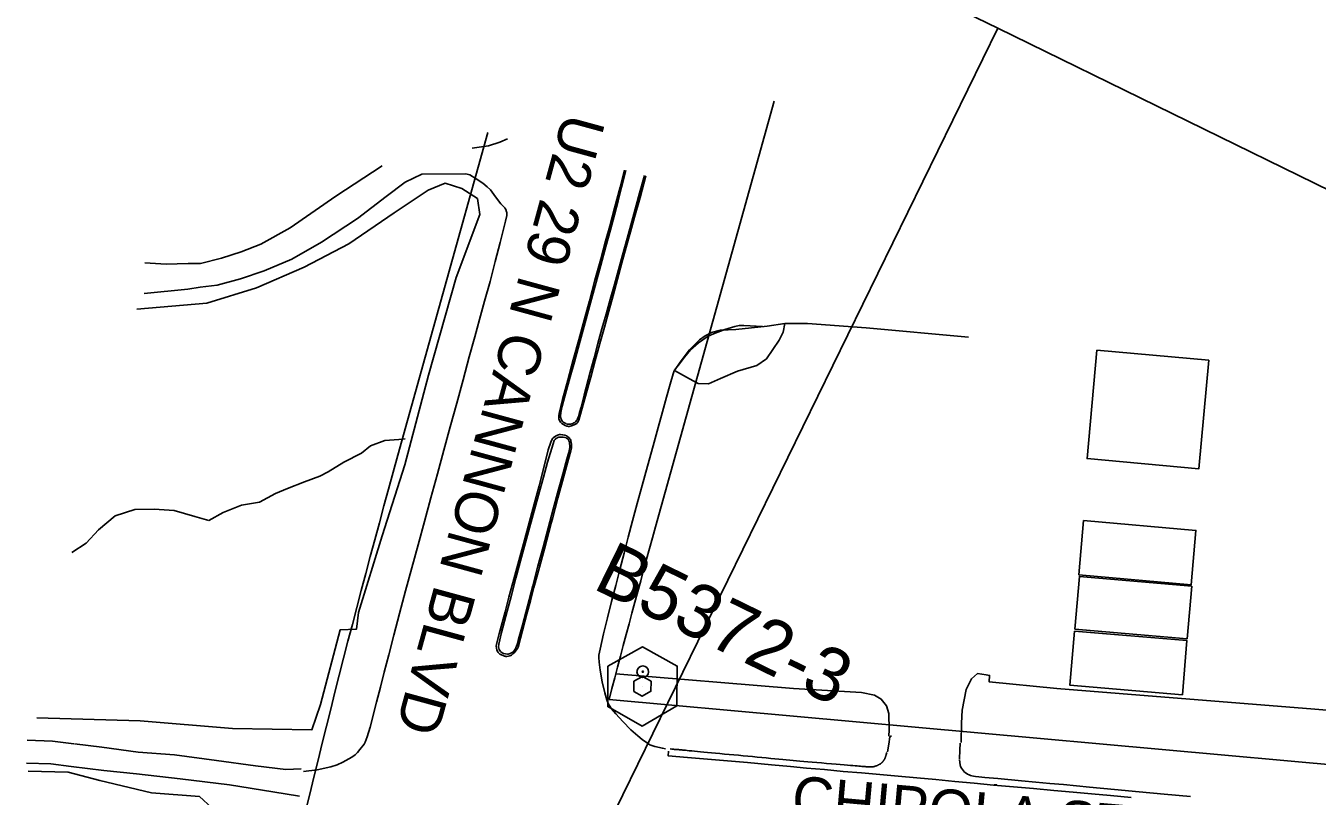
# Model space of a CAD drawing. Extents: x 1517485 to 1521905, y 636528 to 640355.
# Drawn here: x 1520407.4 to 1520890.3, y 638790.2 to 639078.4 of the extents above; entities that cross this region are included whole.
import ezdxf

# ---------------------------------------------------------------- set-up
doc = ezdxf.new("R2010")
doc.units = 0
for name, color, linetype in [('CTL Primary Horizontal and Vertical CELL', 7, 'Continuous'), ('CTL Primary Horizontal and Vertical Text', 7, 'Continuous'), ('Default', 7, 'Continuous'), ('Exist Building Metal Canopy', 7, 'Continuous'), ('Exist Hydro Stream or Body of Water', 7, 'Continuous'), ('Exist Right of Way Line', 7, 'Continuous'), ('Exist Roads Curbs', 7, 'Continuous'), ('Exist Roads EOP', 7, 'Continuous'), ('Exist Roads EOP Other', 7, 'Continuous'), ('Exist Roads EOP Text', 7, 'Continuous'), ('Exist Roads Soil', 7, 'Continuous'), ('Exist Vegetation Woods Line', 7, 'Continuous'), ('Scratch_Level_3', 7, 'Continuous')]:
    doc.layers.add(name, color=color, linetype=linetype)

msp = doc.modelspace()

# ---------------------------------------------------------------- linework, layer by layer
at = {"layer": 'CTL Primary Horizontal and Vertical CELL'}
msp.add_line((1520637.94, 638831.29), (1520637.94, 638831.29), dxfattribs=at)
msp.add_lwpolyline([(1520625.02, 638838.78), (1520638.02, 638846.03), (1520651.02, 638838.88), (1520650.82, 638823.98), (1520637.82, 638816.43), (1520625.02, 638823.68)], close=True, dxfattribs=at)
at = {"layer": 'Default'}
msp.add_line((1520637.94, 638831.29), (1520637.94, 638831.29), dxfattribs=at)
msp.add_lwpolyline([(1520634.71, 638833.16), (1520637.96, 638834.98), (1520641.21, 638833.19), (1520641.16, 638829.46), (1520637.91, 638827.58), (1520634.71, 638829.39)], close=True, dxfattribs=at)
for radius in [2.18, 0.24]:
    msp.add_circle((1520638.12, 638836.73), radius, dxfattribs=at)
at = {"layer": 'Exist Building Metal Canopy'}
for points in [[(1520807.97, 638957.02), (1520849.77, 638953.23), (1520846.08, 638912.69), (1520804.27, 638916.48)], [(1520802.95, 638893.33), (1520844.95, 638889.59), (1520843.14, 638869.31), (1520801.14, 638873.05)], [(1520841.7, 638849), (1520799.69, 638852.67), (1520801.41, 638872.41), (1520843.42, 638868.74)], [(1520799.56, 638851.92), (1520841.61, 638848.38), (1520839.9, 638828.12), (1520797.85, 638831.66)]]:
    msp.add_lwpolyline(points, close=True, dxfattribs=at)
at = {"layer": 'Exist Hydro Stream or Body of Water'}
for points in [[(1520475.78, 638893.36), (1520481.2, 638896.26), (1520488, 638899.1), (1520494.8, 638900.19), (1520500.81, 638903.46), (1520505.27, 638905.3), (1520511.57, 638907.78), (1520517.29, 638909.85), (1520520.5, 638911.55), (1520526.36, 638915.15), (1520532.89, 638918.5), (1520536.28, 638921.26), (1520541.69, 638923.18), (1520546.85, 638923.62), (1520549.25, 638923.85)], [(1520475.78, 638893.36), (1520470.63, 638894.79), (1520462.91, 638897.11), (1520455.32, 638897.57), (1520448.13, 638897.4), (1520440.85, 638895.01), (1520434.56, 638889.88), (1520429.96, 638884.82), (1520424.55, 638881.35)]]:
    msp.add_lwpolyline(points, dxfattribs=at)
at = {"layer": 'Exist Right of Way Line'}
for p, q in [((1520687.22, 639050.19), (1520642.88, 638890.91)), ((1520580.17, 639038.51), (1520546.55, 638917.73)), ((1520625.53, 638826.37), (1520958.51, 638796.3))]:
    msp.add_line(p, q, dxfattribs=at)
for radius, end in [(3851.74, 170.68088), (3751.74, 165.46414)]:
    msp.add_arc((1524257.18, 637884.74), radius, 164.44356, end, dxfattribs=at)
at = {"layer": 'Exist Roads Curbs'}
for points in [[(1520638.7, 639022.42), (1520636.89, 639015.82), (1520634.37, 639006.59), (1520632.25, 638998.85), (1520630.54, 638992.59), (1520629.03, 638987.06), (1520627.5, 638981.54), (1520625.95, 638976.01), (1520624.39, 638970.48), (1520622.85, 638964.97), (1520621.35, 638959.51), (1520619.89, 638954.11), (1520618.47, 638948.76), (1520616.22, 638940.17), (1520615.03, 638935.72), (1520614.46, 638933.66), (1520614.06, 638932.25), (1520613.73, 638931.31), (1520613.56, 638930.96), (1520613.38, 638930.69), (1520613.04, 638930.31), (1520612.9, 638930.17), (1520612.64, 638930.01), (1520612.33, 638929.83), (1520611.97, 638929.63), (1520611.58, 638929.46), (1520611.16, 638929.33), (1520610.93, 638929.3), (1520610.43, 638929.29), (1520609.94, 638929.35), (1520609.49, 638929.45), (1520609.27, 638929.54), (1520608.79, 638929.79), (1520608.53, 638929.96), (1520608.27, 638930.17), (1520608.05, 638930.41), (1520607.85, 638930.69), (1520607.68, 638930.99), (1520607.55, 638931.31), (1520607.45, 638931.62), (1520607.39, 638931.92), (1520607.37, 638932.48), (1520607.39, 638932.91), (1520607.43, 638933.25), (1520607.5, 638933.66), (1520607.61, 638934.33), (1520608.02, 638936.03), (1520608.87, 638939.35), (1520610.96, 638947.02), (1520612.53, 638952.65), (1520614.31, 638959.11), (1520616.21, 638966.01), (1520618.21, 638973.36), (1520620.33, 638981.15), (1520622.4, 638988.82), (1520624.29, 638995.8), (1520625.99, 639002.09), (1520627.5, 639007.7), (1520628.88, 639012.89), (1520630.18, 639017.93), (1520631.71, 639024.21)], [(1520729.39, 638806.53), (1520729.15, 638805.75), (1520729.09, 638805.56), (1520729.05, 638805.43), (1520729, 638805.3), (1520728.96, 638805.18), (1520728.93, 638805.07), (1520728.89, 638804.97), (1520728.85, 638804.87), (1520728.82, 638804.77), (1520728.78, 638804.67), (1520728.74, 638804.57), (1520728.7, 638804.47), (1520728.66, 638804.37), (1520728.61, 638804.27), (1520728.57, 638804.17), (1520728.52, 638804.06), (1520728.47, 638803.96), (1520728.42, 638803.86), (1520728.37, 638803.77), (1520728.31, 638803.67), (1520728.25, 638803.58), (1520728.19, 638803.49), (1520728.13, 638803.4), (1520728.06, 638803.31), (1520727.99, 638803.22), (1520727.9, 638803.12), (1520727.81, 638803.02), (1520727.71, 638802.92), (1520727.6, 638802.82), (1520727.49, 638802.71), (1520727.36, 638802.61), (1520727.23, 638802.5), (1520727.1, 638802.39), (1520726.96, 638802.29), (1520726.81, 638802.2), (1520726.66, 638802.11), (1520726.51, 638802.02), (1520726.35, 638801.94), (1520726.19, 638801.86), (1520726.03, 638801.79), (1520725.88, 638801.72), (1520725.73, 638801.65), (1520725.58, 638801.59), (1520725.45, 638801.54), (1520725.31, 638801.49), (1520725.18, 638801.44), (1520725.06, 638801.4), (1520724.94, 638801.37), (1520724.83, 638801.33), (1520724.72, 638801.3), (1520724.61, 638801.27), (1520724.5, 638801.25), (1520724.4, 638801.22), (1520724.3, 638801.2), (1520724.2, 638801.19), (1520724.1, 638801.17), (1520724, 638801.16), (1520723.9, 638801.15), (1520723.8, 638801.14), (1520723.7, 638801.13), (1520723.59, 638801.12), (1520723.48, 638801.12), (1520723.36, 638801.12), (1520723.23, 638801.12), (1520723.08, 638801.12), (1520722.91, 638801.13), (1520722.71, 638801.14), (1520722.49, 638801.15), (1520722.24, 638801.16), (1520721.97, 638801.18), (1520721.66, 638801.2), (1520721.32, 638801.23), (1520720.93, 638801.26), (1520720.5, 638801.29), (1520720.01, 638801.33), (1520719.47, 638801.38), (1520718.89, 638801.43), (1520718.25, 638801.48), (1520717.54, 638801.55), (1520716.72, 638801.62), (1520715.77, 638801.7), (1520714.67, 638801.8), (1520713.4, 638801.9), (1520711.98, 638802.02), (1520710.41, 638802.16), (1520708.67, 638802.31), (1520706.84, 638802.46), (1520704.99, 638802.62), (1520703.17, 638802.77), (1520701.45, 638802.92), (1520699.83, 638803.06), (1520698.31, 638803.19), (1520696.89, 638803.32), (1520695.57, 638803.43), (1520694.31, 638803.55), (1520693.06, 638803.66), (1520691.79, 638803.78), (1520690.43, 638803.9), (1520689.01, 638804.03), (1520687.51, 638804.18), (1520685.94, 638804.33), (1520684.3, 638804.48), (1520682.6, 638804.65), (1520680.86, 638804.81), (1520679.11, 638804.98), (1520677.36, 638805.15), (1520675.6, 638805.31), (1520673.85, 638805.48), (1520672.11, 638805.64), (1520670.36, 638805.8), (1520668.63, 638805.96), (1520666.95, 638806.12), (1520665.33, 638806.27), (1520663.8, 638806.41), (1520662.35, 638806.55), (1520660.99, 638806.68), (1520659.71, 638806.8), (1520658.51, 638806.92), (1520657.41, 638807.03), (1520656.41, 638807.12), (1520655.51, 638807.21), (1520654.72, 638807.29), (1520654.05, 638807.36), (1520653.49, 638807.42), (1520653.04, 638807.46), (1520652.7, 638807.49), (1520652.44, 638807.52), (1520652.25, 638807.54), (1520652.08, 638807.55), (1520651.92, 638807.57), (1520651.76, 638807.58), (1520651.6, 638807.6), (1520651.45, 638807.61), (1520651.29, 638807.62), (1520651.13, 638807.63), (1520650.93, 638807.64), (1520650.69, 638807.66), (1520650.38, 638807.68), (1520650.01, 638807.71), (1520649.58, 638807.75), (1520649.01, 638807.8), (1520648.31, 638807.86)], [(1520756.55, 638803.95), (1520756.63, 638802.78), (1520756.76, 638801.95), (1520756.98, 638801.29), (1520757.27, 638800.7), (1520757.62, 638800.15), (1520758.02, 638799.64), (1520758.47, 638799.18), (1520758.99, 638798.78), (1520759.54, 638798.44), (1520760.11, 638798.18), (1520760.67, 638797.97), (1520761.22, 638797.81), (1520761.82, 638797.68), (1520762.52, 638797.58), (1520763.79, 638797.45), (1520766.05, 638797.22), (1520770.86, 638796.76), (1520779.75, 638795.95), (1520785.15, 638795.46), (1520790.38, 638794.98), (1520795.46, 638794.5), (1520805.2, 638793.57), (1520814.57, 638792.69), (1520823.7, 638791.86), (1520833.15, 638791), (1520842.96, 638790.11)]]:
    msp.add_lwpolyline(points, dxfattribs=at)
msp.add_lwpolyline([(1520609.34, 638914.83), (1520608.2, 638910.7), (1520606.61, 638904.88), (1520604.64, 638897.61), (1520602.7, 638890.39), (1520600.83, 638883.4), (1520598.92, 638876.23), (1520596.96, 638868.83), (1520594.97, 638861.32), (1520593.07, 638854.15), (1520591.92, 638849.84), (1520591.52, 638848.38), (1520591.21, 638847.34), (1520590.9, 638846.35), (1520590.64, 638845.62), (1520590.42, 638845.15), (1520590.17, 638844.78), (1520589.89, 638844.47), (1520589.58, 638844.18), (1520589.25, 638843.91), (1520588.77, 638843.65), (1520588.47, 638843.51), (1520588.14, 638843.4), (1520587.81, 638843.33), (1520587.46, 638843.31), (1520586.77, 638843.38), (1520586.19, 638843.5), (1520585.95, 638843.58), (1520585.72, 638843.7), (1520585.47, 638843.87), (1520584.92, 638844.37), (1520584.65, 638844.71), (1520584.44, 638845.1), (1520584.29, 638845.55), (1520584.2, 638846.06), (1520584.27, 638847.01), (1520585.24, 638851.42), (1520587.33, 638859.34), (1520588.84, 638864.94), (1520590.67, 638871.71), (1520592.81, 638879.62), (1520595.04, 638887.86), (1520597.14, 638895.58), (1520599.1, 638902.79), (1520600.93, 638909.48), (1520602.51, 638915.16), (1520604.55, 638922.03), (1520605.01, 638923.22), (1520605.3, 638923.61), (1520605.63, 638923.93), (1520605.98, 638924.17), (1520606.36, 638924.34), (1520606.76, 638924.44), (1520607.16, 638924.5), (1520607.56, 638924.52), (1520608.35, 638924.44), (1520608.97, 638924.33), (1520609.42, 638924.19), (1520609.62, 638924.1), (1520609.81, 638923.98), (1520610, 638923.84), (1520610.17, 638923.68), (1520610.31, 638923.5), (1520610.42, 638923.3), (1520610.51, 638923.08), (1520610.64, 638922.57), (1520610.75, 638921.96), (1520610.8, 638921.32), (1520610.77, 638920.68), (1520610.69, 638920.06), (1520610.58, 638919.46), (1520610.43, 638918.79), (1520610.21, 638917.98), (1520609.74, 638916.28)], close=True, dxfattribs=at)
at = {"layer": 'Exist Roads EOP'}
msp.add_line((1520770.49, 638794.38), (1520769.51, 638794.47), dxfattribs=at)
for points in [[(1520587.48, 639036.07), (1520584.67, 639034.8), (1520580.41, 639033.48), (1520574.3, 639032.58)], [(1520571.88, 639023.01), (1520573.39, 639022.56), (1520575.78, 639021.1), (1520578.24, 639019.52), (1520579.92, 639018.18), (1520581.11, 639016.96), (1520583.06, 639014.43), (1520585.02, 639011.81), (1520586.49, 639010.27), (1520586.7, 639009.97), (1520586.84, 639009.7), (1520587.2, 639008.76), (1520587.26, 639008.55), (1520587.3, 639008.36), (1520587.32, 639008.17), (1520587.23, 639007.41), (1520586.77, 639005.26), (1520584.78, 638997.34), (1520582.94, 638990.21), (1520580.97, 638982.76), (1520578.95, 638975.36), (1520577.06, 638968.5), (1520575.26, 638962.01), (1520573.22, 638954.53), (1520570.9, 638945.98), (1520568.52, 638937.22), (1520566.1, 638928.41), (1520563.7, 638919.57), (1520561.3, 638910.71), (1520558.88, 638901.81), (1520556.45, 638892.9), (1520554.06, 638884.17), (1520551.7, 638875.61), (1520549.38, 638867.03), (1520547.1, 638858.48), (1520544.99, 638850.46), (1520543.08, 638843.09), (1520541.42, 638836.63), (1520539.97, 638830.98), (1520538.53, 638825.33), (1520536.11, 638815.97), (1520535.09, 638812.41), (1520534.29, 638810.43), (1520533.87, 638809.68), (1520532.34, 638807.59), (1520531.43, 638806.57), (1520530.49, 638805.68), (1520529.3, 638804.8), (1520525.96, 638802.93), (1520523.77, 638801.94), (1520521.5, 638801.15), (1520516.28, 638800.03), (1520511.28, 638799.4)], [(1520631.21, 639024.33), (1520629.66, 639018.04), (1520627.54, 639010.13), (1520625.73, 639003.47), (1520624.2, 638997.84), (1520622.37, 638991.11), (1520620.21, 638983.17), (1520618.12, 638975.51), (1520616.15, 638968.29), (1520614.15, 638960.94), (1520612.09, 638953.4), (1520610.04, 638945.81), (1520608.12, 638938.63), (1520606.78, 638933.31), (1520606.7, 638932.49), (1520606.7, 638931.61), (1520606.77, 638931.2), (1520606.9, 638930.81), (1520607.07, 638930.46), (1520607.29, 638930.15), (1520607.54, 638929.86), (1520607.82, 638929.61), (1520608.44, 638929.2), (1520609.08, 638928.88), (1520609.71, 638928.65), (1520610, 638928.57), (1520610.28, 638928.54), (1520610.53, 638928.54), (1520611, 638928.59), (1520611.46, 638928.71), (1520612.48, 638929.11), (1520612.99, 638929.36), (1520613.39, 638929.64), (1520613.55, 638929.8), (1520613.71, 638929.97), (1520613.97, 638930.37), (1520614.2, 638930.87), (1520614.87, 638933.13), (1520617.06, 638941.19), (1520618.63, 638946.94), (1520620.35, 638953.22), (1520622.07, 638959.51), (1520623.77, 638965.68), (1520625.39, 638971.6), (1520626.99, 638977.49), (1520628.65, 638983.57), (1520630.31, 638989.65), (1520631.92, 638995.54), (1520633.49, 639001.27), (1520635.03, 639006.83), (1520637.07, 639014.18), (1520639.31, 639022.26)], [(1520682.86, 638965.85), (1520675.86, 638966.3), (1520674.14, 638966.21), (1520672.49, 638965.91), (1520668.83, 638964.8), (1520664.61, 638963.2), (1520662.52, 638962.21), (1520658.91, 638959.79), (1520655.9, 638957.11), (1520653.7, 638954.45), (1520651.83, 638951.88), (1520650.86, 638950.64), (1520650.02, 638949.53), (1520649.89, 638949.26), (1520649.52, 638948.13), (1520648.39, 638944.27), (1520647.02, 638939.46), (1520645.49, 638934.01), (1520643.84, 638928.06), (1520641.95, 638921.25), (1520639.83, 638913.7), (1520637.85, 638906.45), (1520636.04, 638899.67), (1520634.32, 638893.25), (1520632.68, 638887.13), (1520631.09, 638881.07), (1520629.52, 638875.02), (1520627.98, 638869.01), (1520626.46, 638863.02), (1520624.91, 638856.88), (1520623.43, 638850.87), (1520622.11, 638845.2), (1520621.73, 638842.95), (1520621.66, 638842.08), (1520621.75, 638840.29), (1520622.18, 638837.3), (1520622.94, 638833.02), (1520623.88, 638828.84), (1520624.68, 638826.22), (1520625.22, 638824.89), (1520625.54, 638824.25), (1520626.47, 638822.89), (1520628.01, 638820.99), (1520630.59, 638818.16), (1520633.69, 638814.98), (1520636.2, 638812.7), (1520637.87, 638811.34), (1520639.81, 638809.98), (1520640.78, 638809.43), (1520642.62, 638808.73), (1520645.45, 638808.1), (1520646.56, 638807.9)], [(1520820.72, 638789.68), (1520812.98, 638790.38), (1520805.95, 638791.02), (1520799.06, 638791.65), (1520791.78, 638792.31), (1520784.29, 638793), (1520776.73, 638793.68), (1520769.26, 638794.36), (1520762, 638795.05), (1520754.85, 638795.73), (1520747.68, 638796.37), (1520740.59, 638796.99), (1520733.67, 638797.62), (1520726.82, 638798.25), (1520719.93, 638798.86), (1520713.01, 638799.48), (1520706.03, 638800.11), (1520699.38, 638800.72), (1520693.41, 638801.26), (1520686.29, 638801.93), (1520677.29, 638802.76), (1520669.79, 638803.43), (1520662.26, 638804.08), (1520654.81, 638804.71), (1520647.54, 638805.34), (1520647.73, 638807.02)]]:
    msp.add_lwpolyline(points, dxfattribs=at)
msp.add_lwpolyline([(1520604.33, 638893.89), (1520606.39, 638901.62), (1520608.51, 638909.39), (1520610.34, 638916.2), (1520611.19, 638919.41), (1520611.41, 638920.51), (1520611.42, 638921.81), (1520611.36, 638922.49), (1520611.23, 638923.12), (1520611.14, 638923.39), (1520611.02, 638923.64), (1520610.88, 638923.86), (1520610.54, 638924.26), (1520610.13, 638924.65), (1520609.88, 638924.82), (1520609.6, 638924.98), (1520608.91, 638925.25), (1520608.14, 638925.42), (1520607.38, 638925.46), (1520606.99, 638925.43), (1520606.61, 638925.35), (1520606.23, 638925.22), (1520605.49, 638924.87), (1520604.92, 638924.49), (1520604.72, 638924.31), (1520604.53, 638924.09), (1520604.14, 638923.46), (1520603.71, 638922.57), (1520602.77, 638919.69), (1520600.69, 638911.65), (1520599.3, 638906.29), (1520597.82, 638900.77), (1520595.7, 638892.93), (1520593.82, 638885.99), (1520592.46, 638881), (1520590.97, 638875.5), (1520589.5, 638870.04), (1520588.04, 638864.61), (1520586.58, 638859.21), (1520584.36, 638850.95), (1520583.36, 638847), (1520583.32, 638846.3), (1520583.39, 638845.6), (1520583.56, 638844.88), (1520583.69, 638844.54), (1520583.84, 638844.23), (1520584.02, 638843.95), (1520584.23, 638843.71), (1520584.45, 638843.5), (1520584.68, 638843.32), (1520584.92, 638843.18), (1520585.9, 638842.77), (1520586.36, 638842.59), (1520586.6, 638842.53), (1520586.83, 638842.5), (1520587.32, 638842.49), (1520587.86, 638842.56), (1520588.44, 638842.7), (1520588.73, 638842.82), (1520589.01, 638842.98), (1520589.55, 638843.38), (1520590.06, 638843.86), (1520590.89, 638844.93), (1520591.21, 638845.45), (1520591.45, 638845.96), (1520592.38, 638849.25), (1520594.79, 638858.39), (1520596.09, 638863.3), (1520597.4, 638868.23), (1520598.73, 638873.14), (1520601.33, 638882.74), (1520603.9, 638892.29)], close=True, dxfattribs=at)
at = {"layer": 'Exist Roads EOP Other'}
msp.add_line((1520436.49, 638799.75), (1520424.32, 638801.3), dxfattribs=at)
for points in [[(1520540.66, 639026.05), (1520523.32, 639014.59), (1520506.27, 639002.85), (1520495.29, 638996.74), (1520487.92, 638993.82), (1520480.53, 638991.49), (1520472.69, 638989.48)], [(1520451.63, 638978.2), (1520467.94, 638979.89), (1520472.52, 638980.64), (1520478.97, 638981.34), (1520487.71, 638983.73), (1520496.57, 638986.76), (1520506.91, 638991.03), (1520517.94, 638997.45), (1520531.38, 639006.24), (1520542.15, 639014.56), (1520549.29, 639019.83), (1520555.43, 639022.9), (1520571.88, 639023.01)], [(1520451.84, 638989.66), (1520459.84, 638989.15), (1520468.03, 638989.48), (1520472.69, 638989.48)], [(1520759.91, 638961.9), (1520721.59, 638965.42), (1520699.73, 638966.96), (1520691.22, 638966.99), (1520684.57, 638965.96), (1520672.86, 638964.71)], [(1520649.95, 638949.38), (1520652.08, 638952.59), (1520655.56, 638957.12), (1520659.34, 638960.87), (1520661.49, 638962.4), (1520663.77, 638963.62), (1520667.12, 638964.46), (1520672.86, 638964.71)], [(1520731.18, 638812.71), (1520730.46, 638812.35), (1520730.12, 638809.68), (1520729.61, 638806.82)], [(1520425.38, 638809.79), (1520417.38, 638810.79), (1520407.83, 638811.08)], [(1520510.41, 638800.44), (1520504.56, 638800.11), (1520493.25, 638801.49), (1520478.66, 638803.55), (1520462.94, 638805.7), (1520449.44, 638806.7), (1520435.83, 638808.51), (1520425.53, 638809.77)], [(1520756.56, 638804.1), (1520756.68, 638807.41), (1520756.8, 638809.99)], [(1520424.32, 638801.3), (1520416.72, 638802.25), (1520407.57, 638802.52)], [(1520509.75, 638790.2), (1520499.81, 638791.79), (1520483.54, 638794.48), (1520465.12, 638796.69), (1520448.8, 638798.51), (1520436.49, 638799.75)]]:
    msp.add_lwpolyline(points, dxfattribs=at)
at = {"layer": 'Exist Roads Soil'}
for points in [[(1520691.22, 638966.99), (1520690.65, 638963.74), (1520689.06, 638960.8), (1520684.42, 638953.8), (1520680.7, 638951.24), (1520673.5, 638949.23), (1520667.19, 638946.43), (1520662.66, 638944.46), (1520658.82, 638944.56), (1520655.58, 638946.31), (1520649.95, 638949.38)], [(1520793.01, 638830.44), (1520839.55, 638826.71), (1520887.89, 638822.86), (1520936.28, 638818.92), (1520944.44, 638927)], [(1520730.09, 638812.68), (1520730.2, 638815), (1520730.17, 638821.14), (1520729.31, 638823.97), (1520727.3, 638826.51), (1520724.76, 638827.93), (1520719.9, 638828.95), (1520694.44, 638830.41), (1520628.05, 638836.01)], [(1520757.21, 638810.25), (1520757.32, 638817.49), (1520757.54, 638822.4), (1520759.08, 638830.06), (1520761.1, 638834.11), (1520763.27, 638836.02), (1520766.48, 638835.63)], [(1520766.48, 638835.63), (1520767.83, 638835.36), (1520767.71, 638832.92), (1520793.01, 638830.44)]]:
    msp.add_lwpolyline(points, dxfattribs=at)
at = {"layer": 'Exist Vegetation Woods Line'}
for points in [[(1520448.83, 638972.33), (1520475.03, 638974.63), (1520493.7, 638980.37), (1520511.42, 638988.05), (1520528.16, 638996.79), (1520545.18, 639008.45), (1520557.82, 639016.89), (1520564.18, 639019.54), (1520570.39, 639017.49), (1520576.27, 639013.73), (1520577.11, 639007.79), (1520568.31, 638984.25), (1520557.95, 638947.7), (1520549.07, 638914.19), (1520540.6, 638887.6), (1520531.77, 638858.87), (1520531.01, 638852.65), (1520524.94, 638852.42), (1520517.56, 638824.52), (1520514.38, 638815.01), (1520484.67, 638815.55), (1520450.12, 638818.33), (1520411.5, 638819.45)], [(1520408.25, 638799.55), (1520423.18, 638799.14), (1520435.06, 638796.1), (1520454.4, 638791.49), (1520472.27, 638790.07), (1520481.6, 638781.65), (1520486.91, 638774.26), (1520490.25, 638766.8), (1520489.8, 638760.35), (1520492.5, 638753.27), (1520492.69, 638750.56), (1520483.5, 638741.02), (1520473.9, 638732.2), (1520463.82, 638719.62), (1520454.95, 638704.9), (1520448.42, 638691.59), (1520449.15, 638683.69), (1520455.48, 638671.17), (1520463.95, 638667.78), (1520468.69, 638667.71)]]:
    msp.add_lwpolyline(points, dxfattribs=at)
at = {"layer": 'Scratch_Level_3'}
for p, q in [((1519835.03, 639535.13), (1520770.84, 639077.45)), ((1520770.84, 639077.45), (1520017.02, 637536.16)), ((1520770.84, 639077.45), (1521706.65, 638619.76))]:
    msp.add_line(p, q, dxfattribs=at)

# ---------------------------------------------------------------- texts
at = {"layer": 'CTL Primary Horizontal and Vertical Text'}
msp.add_text('B5372-3', height=20, rotation=333.9377, dxfattribs=at).set_placement((1520618.93, 638868.08))
at = {"layer": 'Exist Roads EOP Text'}
for s, rotation, p in [('U2 29 N CANNON BLVD', 254.7046, (1520608.69, 639046.36)), ('CHIPOLA ST', 354.8975, (1520693.36, 638781.98))]:
    msp.add_text(s, height=16, rotation=rotation, dxfattribs=at).set_placement(p)

doc.saveas('drawing.dxf')
